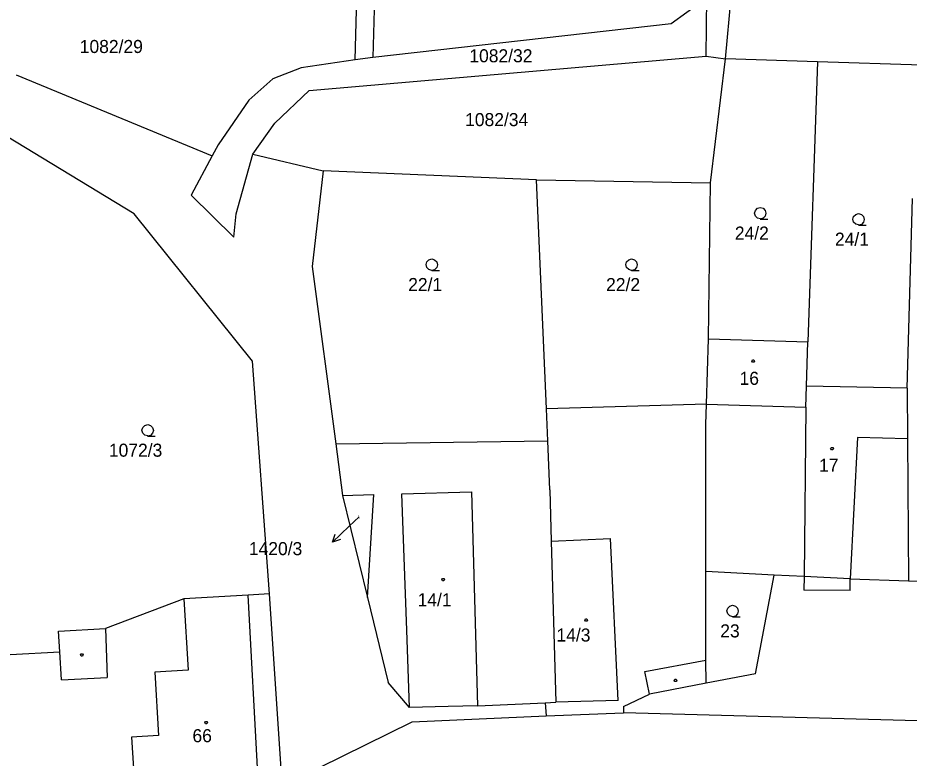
# Model space of a CAD drawing. Extents: x -852001 to -842497, y -1063614 to -1052182.
# Drawn here: x -849610.9 to -849494.9, y -1056343.8 to -1056247.4 of the extents above; entities that cross this region are included whole.
import ezdxf

# ---------------------------------------------------------------- set-up
doc = ezdxf.new("R2010")
doc.units = 0
for name, color, linetype in [('Default', 7, 'Continuous'), ('KN_HRANICE', 7, 'Continuous'), ('KN_KULTURY', 7, 'Continuous'), ('KN_PARCELY', 7, 'Continuous'), ('KN_SLUCKY', 7, 'Continuous')]:
    doc.layers.add(name, color=color, linetype=linetype)

# ---------------------------------------------------------------- blocks, each defined once
blk = doc.blocks.new('304')
at = {"layer": 'Default'}
blk.add_lwpolyline([(0, 0), (-0.38, 0.1), (-0.65, 0.37), (-0.75, 0.74), (-0.65, 1.11), (-0.38, 1.38), (-0.01, 1.48), (0.36, 1.38), (0.63, 1.11), (0.73, 0.73), (0.63, 0.35), (0.36, 0.08), (-0.02, -0.02), (0.98, -0.02)], dxfattribs=at)
blk = doc.blocks.new('10292')
at = {"layer": 'Default'}
blk.add_line((0, 3), (0, 0), dxfattribs=at)
blk.add_lwpolyline([(-0.5, 2), (0, 3), (0.5, 2)], dxfattribs=at)
blk = doc.blocks.new('402')
at = {"layer": 'Default'}
blk.add_lwpolyline([(0.09, 0.15), (0.18, 0), (0.09, -0.15), (-0.09, -0.15), (-0.18, 0), (-0.09, 0.15), (0.09, 0.15)], dxfattribs=at)

msp = doc.modelspace()

# ---------------------------------------------------------------- linework, layer by layer
at = {"layer": 'KN_HRANICE'}
for p, q in [((-849567, -1056252.9), (-849566.03, -1056221.45)), ((-849567, -1056252.9), (-849566.03, -1056221.45)), ((-849563.83, -1056221.55), (-849564.68, -1056252.6)), ((-849563.83, -1056221.55), (-849564.68, -1056252.6)), ((-849521.28, -1056252.42), (-849521.22, -1056244.23)), ((-849521.28, -1056252.42), (-849521.22, -1056244.23)), ((-849518.79, -1056252.77), (-849517.97, -1056244.08)), ((-849518.79, -1056252.77), (-849517.97, -1056244.08)), ((-849521.78, -1056245.26), (-849525.87, -1056248.18)), ((-849521.78, -1056245.26), (-849525.87, -1056248.18)), ((-849525.87, -1056248.18), (-849564.68, -1056252.6)), ((-849525.87, -1056248.18), (-849564.68, -1056252.6)), ((-849567, -1056252.9), (-849574.02, -1056253.95)), ((-849567, -1056252.9), (-849574.02, -1056253.95)), ((-849572.97, -1056256.89), (-849521.28, -1056252.42)), ((-849572.97, -1056256.89), (-849521.28, -1056252.42)), ((-849564.68, -1056252.6), (-849567, -1056252.9)), ((-849564.68, -1056252.6), (-849567, -1056252.9)), ((-849521.28, -1056252.42), (-849518.79, -1056252.77)), ((-849521.28, -1056252.42), (-849518.79, -1056252.77)), ((-849520.73, -1056268.91), (-849518.79, -1056252.77)), ((-849520.73, -1056268.91), (-849518.79, -1056252.77)), ((-849506.8, -1056253.15), (-849518.79, -1056252.77)), ((-849506.8, -1056253.15), (-849518.79, -1056252.77)), ((-849506.8, -1056253.15), (-849508.04, -1056289.59)), ((-849506.8, -1056253.15), (-849508.04, -1056289.59)), ((-849493.22, -1056253.57), (-849506.8, -1056253.15)), ((-849493.22, -1056253.57), (-849506.8, -1056253.15)), ((-849574.02, -1056253.95), (-849577.71, -1056255.35)), ((-849574.02, -1056253.95), (-849577.71, -1056255.35)), ((-849611.09, -1056254.85), (-849585.58, -1056265.38)), ((-849611.09, -1056254.85), (-849585.58, -1056265.38)), ((-849577.71, -1056255.35), (-849580.82, -1056258.14)), ((-849577.71, -1056255.35), (-849580.82, -1056258.14)), ((-849577.42, -1056261.13), (-849572.97, -1056256.89)), ((-849577.42, -1056261.13), (-849572.97, -1056256.89)), ((-849580.82, -1056258.14), (-849584.82, -1056263.95)), ((-849580.82, -1056258.14), (-849584.82, -1056263.95)), ((-849595.77, -1056272.93), (-849616.86, -1056260.15)), ((-849595.77, -1056272.93), (-849616.86, -1056260.15)), ((-849580.29, -1056265.17), (-849577.42, -1056261.13)), ((-849580.29, -1056265.17), (-849577.42, -1056261.13)), ((-849584.82, -1056263.95), (-849585.58, -1056265.38)), ((-849584.82, -1056263.95), (-849585.58, -1056265.38)), ((-849585.58, -1056265.38), (-849588.32, -1056270.53)), ((-849585.58, -1056265.38), (-849588.32, -1056270.53)), ((-849582.46, -1056272.94), (-849580.29, -1056265.17)), ((-849582.46, -1056272.94), (-849580.29, -1056265.17)), ((-849580.29, -1056265.17), (-849571.14, -1056267.35)), ((-849580.29, -1056265.17), (-849571.14, -1056267.35)), ((-849571.14, -1056267.35), (-849572.59, -1056279.79)), ((-849571.14, -1056267.35), (-849572.59, -1056279.79)), ((-849543.36, -1056268.51), (-849571.14, -1056267.35)), ((-849543.36, -1056268.51), (-849571.14, -1056267.35)), ((-849543.36, -1056268.51), (-849520.73, -1056268.91)), ((-849542.09, -1056298.32), (-849543.36, -1056268.51)), ((-849543.36, -1056268.51), (-849520.73, -1056268.91)), ((-849542.09, -1056298.32), (-849543.36, -1056268.51)), ((-849521, -1056289.21), (-849520.73, -1056268.91)), ((-849521, -1056289.21), (-849520.73, -1056268.91)), ((-849588.32, -1056270.53), (-849582.79, -1056275.99)), ((-849588.32, -1056270.53), (-849582.79, -1056275.99)), ((-849495.12, -1056295.64), (-849494.45, -1056270.95)), ((-849495.12, -1056295.64), (-849494.45, -1056270.95)), ((-849580.33, -1056292.14), (-849595.77, -1056272.93)), ((-849580.33, -1056292.14), (-849595.77, -1056272.93)), ((-849582.79, -1056275.99), (-849582.46, -1056272.94)), ((-849582.79, -1056275.99), (-849582.46, -1056272.94)), ((-849572.59, -1056279.79), (-849569.5, -1056302.91)), ((-849572.59, -1056279.79), (-849569.5, -1056302.91)), ((-849521.24, -1056297.73), (-849521, -1056289.21)), ((-849521.24, -1056297.73), (-849521, -1056289.21)), ((-849521, -1056289.21), (-849508.04, -1056289.59)), ((-849521, -1056289.21), (-849508.04, -1056289.59)), ((-849508.22, -1056295.39), (-849508.04, -1056289.59)), ((-849508.22, -1056295.39), (-849508.04, -1056289.59)), ((-849578.15, -1056322.42), (-849580.33, -1056292.14)), ((-849578.15, -1056322.42), (-849580.33, -1056292.14)), ((-849508.3, -1056298.1), (-849508.22, -1056295.39)), ((-849508.3, -1056298.1), (-849508.22, -1056295.39)), ((-849495.12, -1056295.64), (-849508.22, -1056295.39)), ((-849495.12, -1056295.64), (-849508.22, -1056295.39)), ((-849495.12, -1056295.64), (-849495.08, -1056302.24)), ((-849495.12, -1056295.64), (-849495.08, -1056302.24)), ((-849521.24, -1056297.73), (-849542.09, -1056298.32)), ((-849521.24, -1056297.73), (-849542.09, -1056298.32)), ((-849541.91, -1056302.5), (-849542.09, -1056298.32)), ((-849541.91, -1056302.5), (-849542.09, -1056298.32)), ((-849521.32, -1056300.37), (-849521.24, -1056297.73)), ((-849521.32, -1056300.37), (-849521.24, -1056297.73)), ((-849508.3, -1056298.1), (-849508.54, -1056320.18)), ((-849508.3, -1056298.1), (-849508.54, -1056320.18)), ((-849521.32, -1056319.52), (-849521.32, -1056300.37)), ((-849521.32, -1056319.52), (-849521.32, -1056300.37)), ((-849569.5, -1056302.91), (-849541.91, -1056302.5)), ((-849569.5, -1056302.91), (-849541.91, -1056302.5)), ((-849569.5, -1056302.91), (-849568.61, -1056309.6)), ((-849569.5, -1056302.91), (-849568.61, -1056309.6)), ((-849541.64, -1056308.88), (-849541.91, -1056302.5)), ((-849541.64, -1056308.88), (-849541.91, -1056302.5)), ((-849495.08, -1056302.24), (-849494.97, -1056320.74)), ((-849495.08, -1056302.24), (-849494.97, -1056320.74)), ((-849568.61, -1056309.6), (-849564.57, -1056309.49)), ((-849568.61, -1056309.6), (-849564.57, -1056309.49)), ((-849568.61, -1056309.6), (-849565.38, -1056322.92)), ((-849568.61, -1056309.6), (-849565.38, -1056322.92)), ((-849565.38, -1056322.92), (-849564.57, -1056309.49)), ((-849565.38, -1056322.92), (-849564.57, -1056309.49)), ((-849541.64, -1056308.88), (-849541.45, -1056315.57)), ((-849541.64, -1056308.88), (-849541.45, -1056315.57)), ((-849541.45, -1056315.57), (-849540.85, -1056336.53)), ((-849541.45, -1056315.57), (-849540.85, -1056336.53)), ((-849521.32, -1056331.05), (-849521.32, -1056319.52)), ((-849512.43, -1056319.98), (-849521.32, -1056319.52)), ((-849521.32, -1056331.05), (-849521.32, -1056319.52)), ((-849512.43, -1056319.98), (-849521.32, -1056319.52)), ((-849514.89, -1056332.85), (-849512.43, -1056319.98)), ((-849514.89, -1056332.85), (-849512.43, -1056319.98)), ((-849508.54, -1056320.18), (-849512.43, -1056319.98)), ((-849508.54, -1056320.18), (-849512.43, -1056319.98)), ((-849508.54, -1056320.18), (-849508.59, -1056321.95)), ((-849508.54, -1056320.18), (-849508.59, -1056321.95)), ((-849502.57, -1056321.97), (-849502.53, -1056320.49)), ((-849502.57, -1056321.97), (-849502.53, -1056320.49)), ((-849502.53, -1056320.49), (-849494.97, -1056320.74)), ((-849502.53, -1056320.49), (-849494.97, -1056320.74)), ((-849494.97, -1056320.74), (-849490.92, -1056320.87)), ((-849494.97, -1056320.74), (-849490.92, -1056320.87)), ((-849580.93, -1056322.58), (-849589.28, -1056323.07)), ((-849580.93, -1056322.58), (-849589.28, -1056323.07)), ((-849578.15, -1056322.42), (-849580.93, -1056322.58)), ((-849578.15, -1056322.42), (-849580.93, -1056322.58)), ((-849576.45, -1056347.39), (-849578.15, -1056322.42)), ((-849576.45, -1056347.39), (-849578.15, -1056322.42)), ((-849502.57, -1056321.97), (-849508.59, -1056321.95)), ((-849502.57, -1056321.97), (-849508.59, -1056321.95)), ((-849589.28, -1056323.07), (-849599.48, -1056326.92)), ((-849589.28, -1056323.07), (-849599.48, -1056326.92)), ((-849565.38, -1056322.92), (-849562.7, -1056333.97)), ((-849565.38, -1056322.92), (-849562.7, -1056333.97)), ((-849605.58, -1056327.27), (-849599.48, -1056326.92)), ((-849605.58, -1056327.27), (-849599.48, -1056326.92)), ((-849605.43, -1056329.98), (-849605.58, -1056327.27)), ((-849605.43, -1056329.98), (-849605.58, -1056327.27)), ((-849611.88, -1056330.31), (-849605.43, -1056329.98)), ((-849611.88, -1056330.31), (-849605.43, -1056329.98)), ((-849521.3, -1056334.07), (-849521.32, -1056331.05)), ((-849521.3, -1056334.07), (-849521.32, -1056331.05)), ((-849514.89, -1056332.85), (-849521.3, -1056334.07)), ((-849514.89, -1056332.85), (-849521.3, -1056334.07)), ((-849559.9, -1056337.24), (-849562.7, -1056333.97)), ((-849559.9, -1056337.24), (-849562.7, -1056333.97)), ((-849521.3, -1056334.07), (-849528.68, -1056335.48)), ((-849521.3, -1056334.07), (-849528.68, -1056335.48)), ((-849532.07, -1056337.11), (-849528.68, -1056335.48)), ((-849532.07, -1056337.11), (-849528.68, -1056335.48)), ((-849551.04, -1056336.99), (-849542.24, -1056336.61)), ((-849551.04, -1056336.99), (-849542.24, -1056336.61)), ((-849542.24, -1056336.61), (-849540.85, -1056336.53)), ((-849542.24, -1056336.61), (-849540.85, -1056336.53)), ((-849542.24, -1056336.61), (-849542.14, -1056338.3)), ((-849542.24, -1056336.61), (-849542.14, -1056338.3)), ((-849554.88, -1056337.1), (-849559.9, -1056337.24)), ((-849554.88, -1056337.1), (-849559.9, -1056337.24)), ((-849551.04, -1056336.99), (-849554.88, -1056337.1)), ((-849551.04, -1056336.99), (-849554.88, -1056337.1)), ((-849532.07, -1056337.11), (-849532.06, -1056337.93)), ((-849532.07, -1056337.11), (-849532.06, -1056337.93)), ((-849559.57, -1056339.1), (-849542.14, -1056338.3)), ((-849559.57, -1056339.1), (-849542.14, -1056338.3)), ((-849542.14, -1056338.3), (-849532.06, -1056337.93)), ((-849542.14, -1056338.3), (-849532.06, -1056337.93)), ((-849406.11, -1056341.28), (-849532.06, -1056337.93)), ((-849406.11, -1056341.28), (-849532.06, -1056337.93)), ((-849576.45, -1056347.39), (-849559.57, -1056339.1)), ((-849576.45, -1056347.39), (-849559.57, -1056339.1))]:
    msp.add_line(p, q, dxfattribs=at)
at = {"layer": 'KN_PARCELY'}
msp.add_line((-849566.46, -1056312.38), (-849567.77, -1056313.63), dxfattribs=at)
msp.add_line((-849566.46, -1056312.38), (-849567.77, -1056313.63), dxfattribs=at)
at = {"layer": 'KN_SLUCKY'}
for p, q in [((-849521.24, -1056297.73), (-849508.3, -1056298.1)), ((-849521.24, -1056297.73), (-849508.3, -1056298.1)), ((-849501.58, -1056302.08), (-849502.53, -1056320.49)), ((-849501.58, -1056302.08), (-849502.53, -1056320.49)), ((-849495.08, -1056302.24), (-849501.58, -1056302.08)), ((-849495.08, -1056302.24), (-849501.58, -1056302.08)), ((-849560.9, -1056309.39), (-849551.84, -1056309.15)), ((-849560.9, -1056309.39), (-849551.84, -1056309.15)), ((-849560.26, -1056327.16), (-849560.9, -1056309.39)), ((-849560.26, -1056327.16), (-849560.9, -1056309.39)), ((-849551.84, -1056309.15), (-849551.04, -1056336.99)), ((-849551.84, -1056309.15), (-849551.04, -1056336.99)), ((-849541.45, -1056315.57), (-849533.76, -1056315.2)), ((-849541.45, -1056315.57), (-849533.76, -1056315.2)), ((-849532.75, -1056336.3), (-849533.76, -1056315.2)), ((-849532.75, -1056336.3), (-849533.76, -1056315.2)), ((-849502.53, -1056320.49), (-849508.54, -1056320.18)), ((-849502.53, -1056320.49), (-849508.54, -1056320.18)), ((-849579.67, -1056345.88), (-849580.93, -1056322.58)), ((-849579.67, -1056345.88), (-849580.93, -1056322.58)), ((-849589.28, -1056323.07), (-849588.73, -1056332.37)), ((-849589.28, -1056323.07), (-849588.73, -1056332.37)), ((-849599.48, -1056326.92), (-849599.25, -1056333.3)), ((-849599.48, -1056326.92), (-849599.25, -1056333.3)), ((-849559.9, -1056337.24), (-849560.26, -1056327.16)), ((-849559.9, -1056337.24), (-849560.26, -1056327.16)), ((-849605.22, -1056333.64), (-849605.43, -1056329.98)), ((-849605.22, -1056333.64), (-849605.43, -1056329.98)), ((-849529.28, -1056332.55), (-849521.32, -1056331.05)), ((-849529.28, -1056332.55), (-849521.32, -1056331.05)), ((-849588.73, -1056332.37), (-849593.06, -1056332.62)), ((-849588.73, -1056332.37), (-849593.06, -1056332.62)), ((-849593.06, -1056332.62), (-849592.57, -1056340.88)), ((-849593.06, -1056332.62), (-849592.57, -1056340.88)), ((-849528.68, -1056335.48), (-849529.28, -1056332.55)), ((-849528.68, -1056335.48), (-849529.28, -1056332.55)), ((-849605.22, -1056333.64), (-849599.25, -1056333.3)), ((-849605.22, -1056333.64), (-849599.25, -1056333.3)), ((-849532.75, -1056336.3), (-849540.85, -1056336.53)), ((-849532.75, -1056336.3), (-849540.85, -1056336.53)), ((-849592.57, -1056340.88), (-849596.08, -1056341.09)), ((-849592.57, -1056340.88), (-849596.08, -1056341.09)), ((-849596.08, -1056341.09), (-849595.73, -1056346.69)), ((-849596.08, -1056341.09), (-849595.73, -1056346.69))]:
    msp.add_line(p, q, dxfattribs=at)

# ---------------------------------------------------------------- block references
at = {"layer": 'KN_KULTURY'}
for name, p in [('304', (-849514.24, -1056273.6)), ('304', (-849514.24, -1056273.6)), ('304', (-849501.45, -1056274.39)), ('304', (-849501.45, -1056274.39)), ('304', (-849557, -1056280.3)), ('304', (-849557, -1056280.3)), ('304', (-849531, -1056280.3)), ('304', (-849531, -1056280.3)), ('402', (-849515.19, -1056292.11)), ('402', (-849515.19, -1056292.11)), ('304', (-849593.98, -1056301.87)), ('304', (-849593.98, -1056301.87)), ('402', (-849504.91, -1056303.51)), ('402', (-849504.91, -1056303.51)), ('402', (-849555.53, -1056320.57)), ('402', (-849555.53, -1056320.57)), ('304', (-849517.84, -1056325.4)), ('304', (-849517.84, -1056325.4)), ('402', (-849536.92, -1056325.84)), ('402', (-849536.92, -1056325.84)), ('402', (-849602.56, -1056330.38)), ('402', (-849602.56, -1056330.38)), ('402', (-849525.29, -1056333.7)), ('402', (-849525.29, -1056333.7)), ('402', (-849586.39, -1056339.2)), ('402', (-849586.39, -1056339.2))]:
    msp.add_blockref(name, p, dxfattribs=at)
at = {"layer": 'KN_PARCELY', "rotation": 133.499166}
msp.add_blockref('10292', (-849567.77, -1056313.63), dxfattribs=at)
msp.add_blockref('10292', (-849567.77, -1056313.63), dxfattribs=at)

# ---------------------------------------------------------------- texts
at = {"layer": 'KN_PARCELY'}
for s, p in [('1082/29', (-849602.83, -1056252)), ('1082/29', (-849602.83, -1056252)), ('1082/32', (-849552.12, -1056253.21)), ('1082/32', (-849552.12, -1056253.21)), ('1082/34', (-849552.67, -1056261.52)), ('1082/34', (-849552.67, -1056261.52)), ('24/2', (-849517.56, -1056276.3)), ('24/2', (-849517.56, -1056276.3)), ('24/1', (-849504.53, -1056277.09)), ('24/1', (-849504.53, -1056277.09)), ('22/1', (-849560.08, -1056283)), ('22/1', (-849560.08, -1056283)), ('22/2', (-849534.32, -1056283)), ('22/2', (-849534.32, -1056283)), ('16', (-849516.95, -1056295.21)), ('16', (-849516.95, -1056295.21)), ('1072/3', (-849599.04, -1056304.57)), ('1072/3', (-849599.04, -1056304.57)), ('17', (-849506.6, -1056306.53)), ('17', (-849506.6, -1056306.53)), ('1420/3', (-849580.82, -1056317.39)), ('1420/3', (-849580.82, -1056317.39)), ('14/1', (-849558.86, -1056324.05)), ('14/1', (-849558.86, -1056324.05)), ('14/3', (-849540.78, -1056328.64)), ('14/3', (-849540.78, -1056328.64)), ('23', (-849519.46, -1056328.1)), ('23', (-849519.46, -1056328.1)), ('66', (-849588.16, -1056341.75)), ('66', (-849588.16, -1056341.75))]:
    msp.add_text(s, height=1.7, dxfattribs=at).set_placement(p)
msp.add_text('1420/3', height=0.1, rotation=90.642, dxfattribs=at).set_placement((-849566.46, -1056312.63))
msp.add_text('1420/3', height=0.1, rotation=90.642, dxfattribs=at).set_placement((-849566.46, -1056312.63))

doc.saveas('drawing.dxf')
